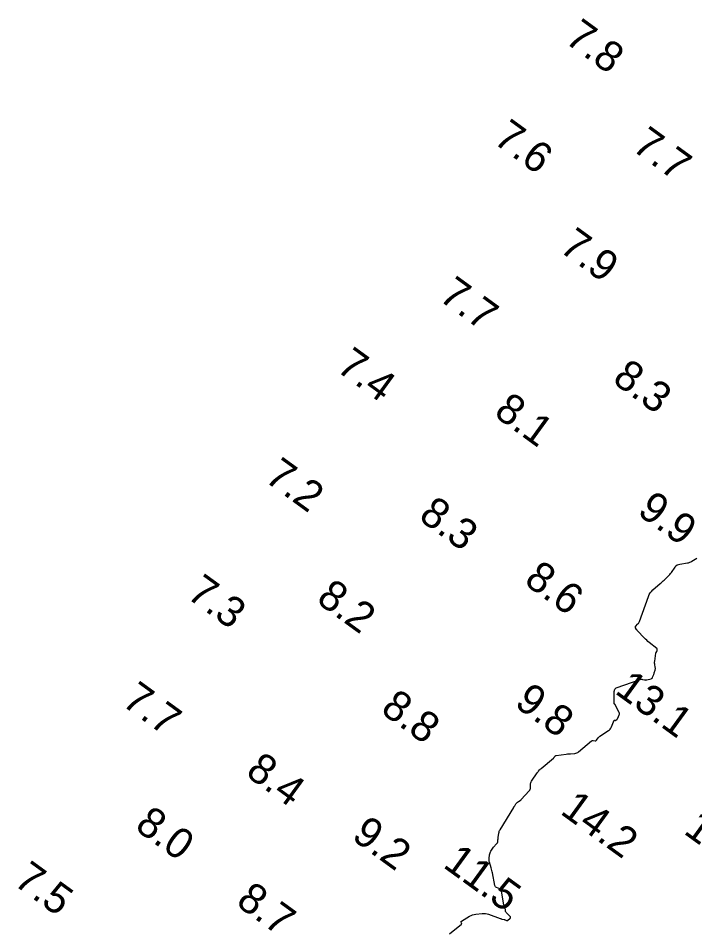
# Model space of a CAD drawing. Extents: x 815352 to 820877, y 582403 to 597439.
# Drawn here: x 817545.5 to 817656.6, y 585697.4 to 585847.5 of the extents above; entities that cross this region are included whole.
import ezdxf

# ---------------------------------------------------------------- set-up
doc = ezdxf.new("R2010")
doc.units = 0
doc.layers.add('V-CONT-EL12', color=7, linetype='Continuous')
doc.layers.add('V-TOPO-SOUN', color=7, linetype='Continuous')

msp = doc.modelspace()

# ---------------------------------------------------------------- linework, layer by layer
at = {"layer": 'V-CONT-EL12'}
for points in [[(817628.04, 585719.09), (817628.08, 585719.14), (817629.4, 585720.6), (817629.48, 585720.71), (817629.54, 585720.83), (817629.58, 585720.96), (817629.59, 585721.09), (817629.6, 585721.66), (817629.61, 585721.79), (817629.64, 585721.92), (817629.69, 585722.05), (817629.76, 585722.17), (817630.7, 585723.55), (817630.75, 585723.61), (817630.8, 585723.67), (817630.84, 585723.73), (817630.9, 585723.79), (817631.1, 585724.03), (817631.16, 585724.09), (817631.21, 585724.14), (817631.27, 585724.2), (817631.33, 585724.25), (817633.37, 585725.93), (817633.41, 585725.96), (817633.45, 585726), (817633.48, 585726.04), (817633.51, 585726.09), (817633.64, 585726.27), (817633.67, 585726.31), (817633.71, 585726.34), (817633.76, 585726.36), (817633.81, 585726.37), (817635.48, 585726.61), (817635.65, 585726.64), (817635.83, 585726.65), (817636, 585726.67), (817636.17, 585726.68), (817636.87, 585726.73), (817637.04, 585726.75), (817637.2, 585726.8), (817637.35, 585726.87), (817637.49, 585726.97), (817639.63, 585728.77), (817639.69, 585728.81), (817639.76, 585728.84), (817639.83, 585728.85), (817639.9, 585728.84), (817640.21, 585728.79), (817640.28, 585728.79), (817640.35, 585728.8), (817640.4, 585728.84), (817640.45, 585728.89), (817640.71, 585729.26), (817640.77, 585729.34), (817640.84, 585729.41), (817640.92, 585729.48), (817641, 585729.54), (817642.39, 585730.47), (817642.55, 585730.59), (817642.68, 585730.73), (817642.79, 585730.89), (817642.88, 585731.07), (817643.32, 585732.16), (817643.33, 585732.18), (817643.34, 585732.19), (817643.36, 585732.19), (817643.37, 585732.18), (817643.45, 585732.13), (817643.47, 585732.12), (817643.48, 585732.12), (817643.5, 585732.12), (817643.52, 585732.13), (817643.79, 585732.31), (817643.83, 585732.34), (817643.87, 585732.39), (817643.91, 585732.44), (817643.93, 585732.49), (817644.16, 585733.07), (817644.2, 585733.19), (817644.2, 585733.3), (817644.18, 585733.42), (817644.13, 585733.53), (817643.43, 585734.79), (817643.43, 585734.81), (817643.42, 585734.82), (817643.41, 585734.83), (817643.39, 585734.84), (817643.34, 585734.87), (817643.33, 585734.88), (817643.33, 585734.89), (817643.32, 585734.9), (817643.32, 585734.91), (817643.35, 585736.64), (817643.34, 585736.66), (817643.34, 585736.68), (817643.34, 585736.7), (817643.34, 585736.72), (817643.32, 585736.8), (817643.32, 585736.82), (817643.32, 585736.84), (817643.32, 585736.86), (817643.33, 585736.88), (817643.47, 585737.27), (817643.5, 585737.34), (817643.54, 585737.39), (817643.6, 585737.44), (817643.66, 585737.47), (817647.63, 585738.87), (817647.71, 585738.9), (817647.8, 585738.91), (817647.89, 585738.9), (817647.98, 585738.89), (817648.33, 585738.8), (817648.42, 585738.79), (817648.51, 585738.78), (817648.59, 585738.79), (817648.68, 585738.81), (817649.41, 585739), (817649.49, 585739.03), (817649.56, 585739.08), (817649.62, 585739.15), (817649.66, 585739.23), (817649.79, 585739.59), (817649.83, 585739.67), (817649.86, 585739.76), (817649.89, 585739.86), (817649.92, 585739.95), (817650.07, 585740.42), (817650.1, 585740.52), (817650.11, 585740.63), (817650.11, 585740.75), (817650.1, 585740.86), (817650.01, 585741.39), (817649.99, 585741.52), (817649.98, 585741.65), (817649.98, 585741.77), (817650, 585741.9), (817650.17, 585743.17), (817650.18, 585743.21), (817650.19, 585743.25), (817650.21, 585743.28), (817650.23, 585743.32), (817650.33, 585743.45), (817650.35, 585743.48), (817650.37, 585743.52), (817650.38, 585743.55), (817650.39, 585743.59), (817650.41, 585743.8), (817650.41, 585743.85), (817650.4, 585743.89), (817650.38, 585743.93), (817650.35, 585743.96), (817649.11, 585744.95), (817648.89, 585745.13), (817648.68, 585745.31), (817648.48, 585745.51), (817648.28, 585745.71), (817647.19, 585746.85), (817647.14, 585746.91), (817647.1, 585746.96), (817647.05, 585747.02), (817647.01, 585747.08), (817646.85, 585747.33), (817646.83, 585747.39), (817646.82, 585747.45), (817646.84, 585747.51), (817646.87, 585747.56), (817647.25, 585747.98), (817647.33, 585748.07), (817647.39, 585748.17), (817647.45, 585748.27), (817647.49, 585748.38), (817648.96, 585752.5), (817649.09, 585752.8), (817649.26, 585753.08), (817649.46, 585753.34), (817649.7, 585753.57), (817650.89, 585754.61), (817651.06, 585754.76), (817651.22, 585754.9), (817651.38, 585755.05), (817651.54, 585755.19), (817652.18, 585755.79), (817652.33, 585755.94), (817652.48, 585756.1), (817652.61, 585756.27), (817652.74, 585756.44), (817653.34, 585757.34), (817653.49, 585757.53), (817653.68, 585757.67), (817653.88, 585757.77), (817654.12, 585757.83), (817655.37, 585758.01), (817655.56, 585758.05), (817655.75, 585758.11), (817655.93, 585758.18), (817656.1, 585758.28), (817656.92, 585758.79)], [(817616.3, 585697.11), (817618.25, 585698.69), (817618.28, 585698.73), (817618.3, 585698.77), (817618.3, 585698.81), (817618.29, 585698.85), (817618.2, 585699.04), (817618.18, 585699.09), (817618.19, 585699.13), (817618.21, 585699.16), (817618.24, 585699.19), (817619.6, 585699.97), (817619.84, 585700.09), (817620.08, 585700.19), (817620.34, 585700.26), (817620.6, 585700.3), (817621.68, 585700.43), (817621.94, 585700.45), (817622.21, 585700.43), (817622.47, 585700.39), (817622.72, 585700.31), (817624.62, 585699.62), (817624.69, 585699.59), (817624.76, 585699.57), (817624.84, 585699.55), (817624.91, 585699.53), (817625.25, 585699.46), (817625.3, 585699.44), (817625.35, 585699.43), (817625.4, 585699.41), (817625.45, 585699.39), (817625.65, 585699.29), (817625.7, 585699.27), (817625.75, 585699.27), (817625.79, 585699.29), (817625.83, 585699.31), (817626.24, 585699.66), (817626.3, 585699.73), (817626.33, 585699.8), (817626.31, 585699.88), (817626.25, 585699.95), (817625.68, 585700.52), (817625.61, 585700.6), (817625.55, 585700.69), (817625.51, 585700.78), (817625.49, 585700.89), (817625.42, 585701.47), (817625.41, 585701.51), (817625.4, 585701.54), (817625.39, 585701.57), (817625.37, 585701.61), (817625.29, 585701.74), (817625.27, 585701.77), (817625.26, 585701.8), (817625.25, 585701.84), (817625.24, 585701.87), (817624.85, 585704.11), (817624.81, 585704.24), (817624.75, 585704.34), (817624.66, 585704.42), (817624.55, 585704.48), (817624.04, 585704.68), (817623.93, 585704.75), (817623.84, 585704.83), (817623.78, 585704.93), (817623.74, 585705.05), (817623.34, 585707.09), (817623.3, 585707.3), (817623.25, 585707.51), (817623.2, 585707.71), (817623.14, 585707.92), (817622.87, 585708.84), (817622.83, 585708.99), (817622.81, 585709.15), (817622.81, 585709.3), (817622.82, 585709.46), (817622.89, 585710.09), (817622.92, 585710.25), (817622.96, 585710.4), (817623.03, 585710.54), (817623.11, 585710.67), (817623.54, 585711.31), (817623.6, 585711.39), (817623.66, 585711.47), (817623.73, 585711.55), (817623.8, 585711.63), (817624.11, 585711.96), (817624.16, 585712.02), (817624.19, 585712.09), (817624.22, 585712.16), (817624.23, 585712.24), (817624.26, 585712.58), (817624.27, 585712.66), (817624.28, 585712.74), (817624.29, 585712.83), (817624.3, 585712.91), (817624.4, 585713.64), (817624.43, 585713.79), (817624.47, 585713.94), (817624.53, 585714.07), (817624.6, 585714.2), (817626.84, 585717.86), (817626.88, 585717.93), (817626.92, 585717.99), (817626.96, 585718.06), (817627, 585718.12), (817627.19, 585718.42), (817627.21, 585718.47), (817627.24, 585718.5), (817627.28, 585718.54), (817627.32, 585718.57), (817627.48, 585718.7), (817627.51, 585718.73), (817627.56, 585718.76), (817627.6, 585718.79), (817627.64, 585718.82), (817627.89, 585718.97), (817627.94, 585719.01), (817627.99, 585719.05), (817628.04, 585719.09)]]:
    msp.add_lwpolyline(points, dxfattribs=at)

# ---------------------------------------------------------------- texts
at = {"layer": 'V-TOPO-SOUN'}
for s, p in [('7.8', (817635.03, 585843.62)), ('7.6', (817623.29, 585827.13)), ('7.7', (817646.06, 585825.94)), ('7.9', (817634.12, 585809.34)), ('7.7', (817614.33, 585801.33)), ('7.4', (817597.5, 585789.69)), ('8.3', (817642.84, 585787.78)), ('8.1', (817623.39, 585782.3)), ('7.2', (817585.72, 585771.58)), ('9.9', (817646.94, 585766.1)), ('8.3', (817611.02, 585765.25)), ('8.6', (817628.34, 585754.69)), ('7.3', (817572.93, 585752.42)), ('8.2', (817594.22, 585751.66)), ('13.1 ', (817643.27, 585736.71)), ('7.7', (817562.27, 585734.8)), ('9.8', (817626.77, 585734.6)), ('8.8', (817604.78, 585733.55)), ('8.4', (817582.61, 585723.22)), ('14.2 ', (817634.3, 585716.94)), ('8.0', (817564.42, 585714.37)), ('12.4 ', (817654.57, 585713.69)), ('9.2', (817600.03, 585712.75)), ('11.5 ', (817615.06, 585708.15)), ('7.5', (817544.51, 585705.3)), ('8.7', (817581.03, 585701.93))]:
    msp.add_text(s, height=5, rotation=324, dxfattribs=at).set_placement(p)

doc.saveas('drawing.dxf')
